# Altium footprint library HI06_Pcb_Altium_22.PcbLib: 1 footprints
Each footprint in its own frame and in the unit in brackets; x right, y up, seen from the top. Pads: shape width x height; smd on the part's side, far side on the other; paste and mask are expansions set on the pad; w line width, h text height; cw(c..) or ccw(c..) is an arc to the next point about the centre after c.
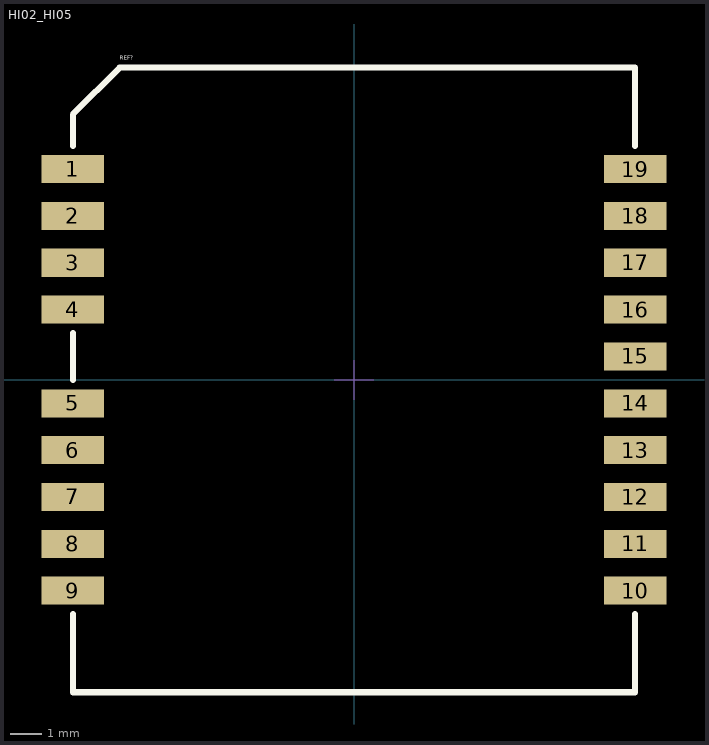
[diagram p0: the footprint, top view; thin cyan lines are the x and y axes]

## HI02_HI05 [mm]
pads (19):
  rect 2x0.9 smd: 1(-9,6.75) 2(-9,5.25) 3(-9,3.75) 4(-9,2.25) 5(-9,-0.75) 6(-9,-2.25) 7(-9,-3.75) 8(-9,-5.25) 9(-9,-6.75) 10(9,-6.75) 11(9,-5.25) 12(9,-3.75) 13(9,-2.25) 14(9,-0.75) 15(9,0.75) 16(9,2.25) 17(9,3.75) 18(9,5.25) 19(9,6.75)
Top Overlay:
  lines w0.2: -9,-7.5 -9,-10 9,-10 9,-7.5 ; -9,0 -9,1.5 ; -9,7.5 -9,8.5 -7.5,10 9,10 9,7.5
  text "REF?" at -7.5,10.25 h0.13
DRAWING_ORIGIN:
  lines w0.025: -0.635,0 0.635,0 ; 0,-0.635 0,0.635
